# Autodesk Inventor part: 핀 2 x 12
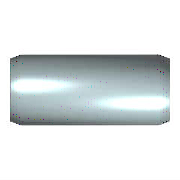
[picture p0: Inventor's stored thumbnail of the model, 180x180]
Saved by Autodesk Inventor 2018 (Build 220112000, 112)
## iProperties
IsCustomPart: 1
Created: 2012-02
Part Number: 핀 2 x 12
Material: 강철, 연강
Description: 평행 핀
Document SubType Name: Modeling
Standard: KS B 1320
Designer: mduedu
Standards Organization: KS
Language: ko-KR
Size Designation: B 2 x  12
Categories: <MemberInstance><Categories><Category DisplayName="조임쇠" InternalName="e4da775c-781d-43d5-af7c-5136215cf5a6" Mnemonic="FSTN"><Category DisplayName="핀" InternalNa
Density: 7.85 g/cm^3
Appearance: 노란색
Mass: 0.29437 g
Surface Area: 0.804998 cm^2
Volume: 0.0374993 cm^3
Author: mduedu
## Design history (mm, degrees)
sketch "스케치"
  geometry: C1 r 1 at (0, 0); 1 further point
  constraints: 1 centre point, 1 coincident
  dimensions: "d1" = 2 diameter of C1 (= NND)
extrude "본체" new body sketch "스케치" distance "d2" = 12 (= NLG); taper "d3" = 0 deg
chamfer "스케치2" distance "d8" = 0.35 (= PHH); stored, may be unused: angle "d9" = 15 deg (= FAWI), second distance "d12" = 0.35 (= PHH)
node "작업 평면1"
node "작업 평면2"
body "Solid1"
chamfer "모따기1" distance "d4" = 0.35 (= PHH); stored, may be unused: angle "d5" = 15 deg (= FAWI), second distance "d11" = 0.35 (= PHH)
other parameters: "NND" = 2 [user parameter; used in 1 equation term], "NLG" = 12 [user parameter; used in 1 equation term], "PHH" = 0.35 [user parameter; used in 4 equation terms], "FAWI" = 15 deg [user parameter; used in 2 equation terms], "d13" = 0, "d15" = 0, "d16" = 0, "KAH" = 0.25 [user parameter]
